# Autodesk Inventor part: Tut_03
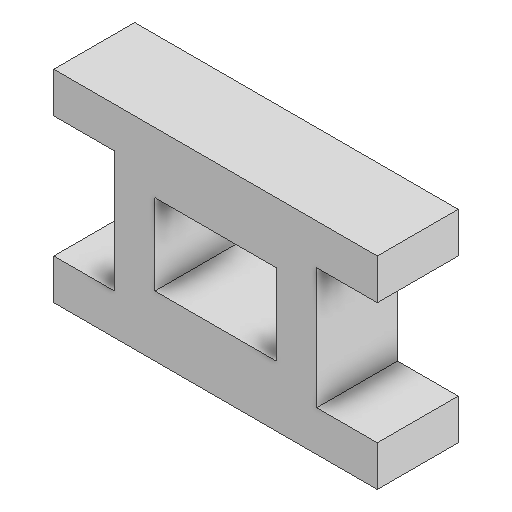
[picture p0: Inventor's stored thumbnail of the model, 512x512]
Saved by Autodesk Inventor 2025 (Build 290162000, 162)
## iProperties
Created: 2022-07
Part Number: Tut_03
Material: Generic
Document SubType Name: Modeling
Designer: LENOVO-CADCIM
Density: 1 g/cm^3
Appearance: Default
Author: LENOVO-CADCIM
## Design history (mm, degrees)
sketch "Sketch1"
  geometry: L1 (0, 0)-(40, 0); L2 (40, 0)-(40, 10); L3 (40, 10)-(25, 10); L4 (25, 10)-(25, 40); L5 (25, 40)-(40, 40); L6 (40, 40)-(40, 50); L7 (40, 50)-(-40, 50); L8 (-40, 50)-(-40, 40); L9 (-40, 40)-(-25, 40); L10 (-25, 40)-(-25, 10); L11 (-25, 10)-(-40, 10); L12 (-40, 10)-(-40, 0); L13 (-40, 0)-(0, 0); L14 (-15, 15)-(15, 15); L15 (15, 15)-(15, 35); L16 (15, 35)-(-15, 35); L17 (-15, 35)-(-15, 15)
  constraints: 34 end point, 13 perpendicular, 2 horizontal, 2 parallel, 1 collinear, 1 point on line
  dimensions: "d0" = 40 distance of L1.start L1.end; "d1" = 10 distance of L1.end L2.end; "d2" = 15 distance of L2.end L3.end; "d3" = 30 distance between parallel lines of L3 L5; "d4" = 15 distance of L4.end L5.end; "d5" = 10 distance of L5.end L6.end; "d6" = 10 distance of L7.end L8.end; "d7" = 15 distance of L8.end L9.end; "d8" = 30 distance of L9.end L10.end; "d9" = 15 distance of L10.end L11.end; "d11" = 20 distance of L16.end L14.start; "d12" = 30 distance of L14.start L14.end; "d13" = 10 distance between parallel lines of L4 L15; "d14" = 15 distance between parallel lines of L14 L1
extrude "Extrusion1" new body sketch "Sketch1" distance "d15" = 20; taper "d16" = 0 deg
body "Solid1"
